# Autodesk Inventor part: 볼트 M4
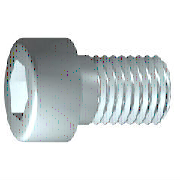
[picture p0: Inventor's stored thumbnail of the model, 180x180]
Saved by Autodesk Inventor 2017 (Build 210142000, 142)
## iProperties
IsCustomPart: 1
Created: 2012-02
Part Number: 볼트 M4
Material: 스테인리스강
Description: 6각 소켓 머리 캡 나사
Document SubType Name: Modeling
Standard: ISO 4762
Designer: mduedu
Standard Revision: Fourth edition 2004-03-01
Standards Organization: ISO
Language: ko-KR
Size Designation: M4 x 10
Categories: <MemberInstance><Categories><Category DisplayName="조임쇠" InternalName="e4da775c-781d-43d5-af7c-5136215cf5a6" Mnemonic="FSTN"><Category DisplayName="볼트" InternalN
Density: 8.08 g/cm^3
Appearance: 반광택
Mass: 2.0939 g
Surface Area: 3.06255 cm^2
Volume: 0.259146 cm^3
Author: mduedu
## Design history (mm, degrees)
sketch "스케치1"
  geometry: L1 (-1, 0)-(10, 0); L2 (10, 0)-(10, 2); L3 (10, 2)-(1.75, 2); L4 (1.75, 2)-(1.32, 2); L5 (1.32, 2)-(0, 2); L6 (0, 2)-(0, 3.5); L7 (0, 3.5)-(-4, 3.5); L8 (-4, 3.5)-(-4, 1.732); L9 (-4, 1.732)-(-2, 1.732); L10 (-2, 1.732)-(-1, 0); L11 (-6.8, 0)-(12.8, 0) reference; L12 (0, -0.7)-(0, 4.2) reference; L13 (1.75, 2)-(0, 2)
  constraints: 22 end point, 6 parallel, 2 collinear, 2 perpendicular, 1 horizontal, 1 point on line
  dimensions: "d1" = 8.25 distance from line of L3.end L2 (= GEL); "d2" = 0.42952 distance of L4.end L3.end (computed from GAL); "d3" = 4 distance between parallel lines of L8 L6 (= KOH); "d4" = 2 distance of L8.end L9.end (= INTI); "d5" = 60 deg angle of L10 L1; "d6" = 4 diameter of L3 L1 (= GD); "d7" = 4 diameter of L5 L1 (= BDM); "d8" = 3.4641 diameter of L9 L1 (= 1.1547 x SW); "d9" = 7 diameter of L7 L1 (= KOD); "d26" = 10 distance between parallel lines of L12 L2 (= NLG)
revolve "본체" sketch "스케치1" stored, may be unused: angle "d10" = 90 deg
sketch "스케치2"
  geometry: L1 (0, -4.9)-(0, 4.9) reference; L2 (-4.9, 0)-(4.9, 0) reference; L3 (1.732, 0)-(0.866, -1.5); L4 (0.866, -1.5)-(-0.866, -1.5); L5 (-0.866, -1.5)-(-1.732, 0); L6 (-1.732, 0)-(-0.866, 1.5); L7 (-0.866, 1.5)-(0.866, 1.5); L8 (0.866, 1.5)-(1.732, 0); 2 further points
  constraints: 12 end point, 1 coincident, 1 horizontal alignment, 1 point on line, 12 other
extrude "슬롯" join sketch "스케치2" stored distance "d11" = 10; taper "d12" = 0 deg
workplane "Work Plane1"
body "Solid1"
fillet "모깎기1" dims "d17" = 0.4 (= RR)
feature "스레드" dims "d13" = 8.25 (= GEL), "d14" = 0
chamfer "모따기1" distance "d15" = 0.42941 (= -0.5 x SPD + 0.5 x GD); stored, may be unused: second distance "d16" = 0.42941 (= GUL), angle "d27" = 45 deg
other parameters: "GD" = 4 [user parameter; used in 2 equation terms], "NLG" = 10 [user parameter; used in 1 equation term], "GEL" = 8.25 [user parameter; used in 2 equation terms], "KOD" = 7 [user parameter; used in 1 equation term], "KOH" = 4 [user parameter; used in 1 equation term], "INTI" = 2 [user parameter; used in 1 equation term], "GAL" = 0.42941 (= 0.61345 x PTC) [user parameter; used in 1 equation term], "GUL" = 0.42941 (= 0.61345 x PTC) [user parameter; used in 1 equation term], "BDM" = 4 (= NND) [user parameter; used in 1 equation term], "SW" = 3 [user parameter; used in 2 equation terms], "RR" = 0.4 [user parameter; used in 1 equation term], "SPD" = 3.14117 (= NND - 1.2269 x PTC) [user parameter; used in 1 equation term], "d19" = 0, "d28" = 0, "d29" = 0, "R" = 0.1 [user parameter], "TOA" = 30 deg [user parameter], "GD1" = 3.14117 (= THREADDIA - 1.2269 x PTC) [user parameter], "THREADDIA" = 4 [user parameter; used in 1 equation term], "FAWI" = 45 deg [user parameter], "TPU" = 14.28571 (computed from PTC) [user parameter], "PTC" = 0.7 [user parameter; used in 5 equation terms], "NND" = 4 [user parameter; used in 2 equation terms], "E0" = 3.465 (= 1.155 x SW) [user parameter]
